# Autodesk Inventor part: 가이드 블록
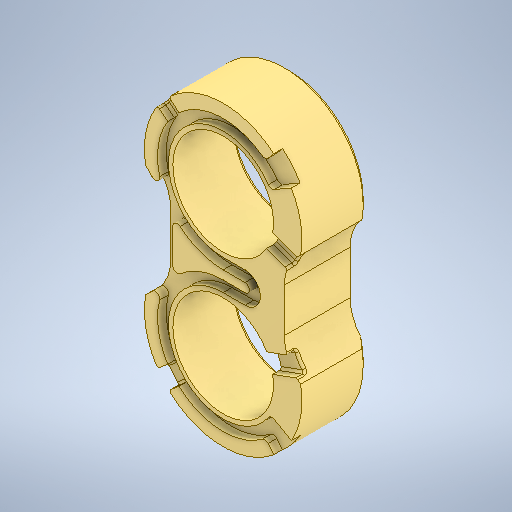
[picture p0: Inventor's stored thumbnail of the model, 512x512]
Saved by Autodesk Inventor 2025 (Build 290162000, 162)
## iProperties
Created: 2026-08
Part Number: 가이드 블록
Material: 강철, 주조
Document SubType Name: Modeling
Designer: KDI
Density: 7.85 g/cm^3
Appearance: 반연마
Mass: 128.923 g
Surface Area: 75.2608 cm^2
Volume: 16.4233 cm^3
Sending System: Autodesk Inventor 2027
Preprocessor: ST-DEVELOPER v20.1
Author: jhkim
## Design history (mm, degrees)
feature "솔리드1"
node "솔리드2"
